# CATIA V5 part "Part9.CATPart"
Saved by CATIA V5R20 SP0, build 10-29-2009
Part number: 9SA120014-T
Revision: ANY
Definition: UNKNOWN
Nomenclature: 9SA120014-T
Source: Unknown
Bounding box of the stored display mesh (mm): x -4.5 to 4.5, y 0 to 5.95, z -4.5 to 4.5
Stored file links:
  C:\Users\Utente\Desktop\IO LAVORO\3D X SITO CF\CUMSA\3D files SA\SA 120314\Part9.CATPart
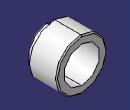
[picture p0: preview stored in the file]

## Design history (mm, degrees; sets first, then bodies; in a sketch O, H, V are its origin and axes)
Body1 "Chaflán1" (main body)
  Solid1: solid without history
